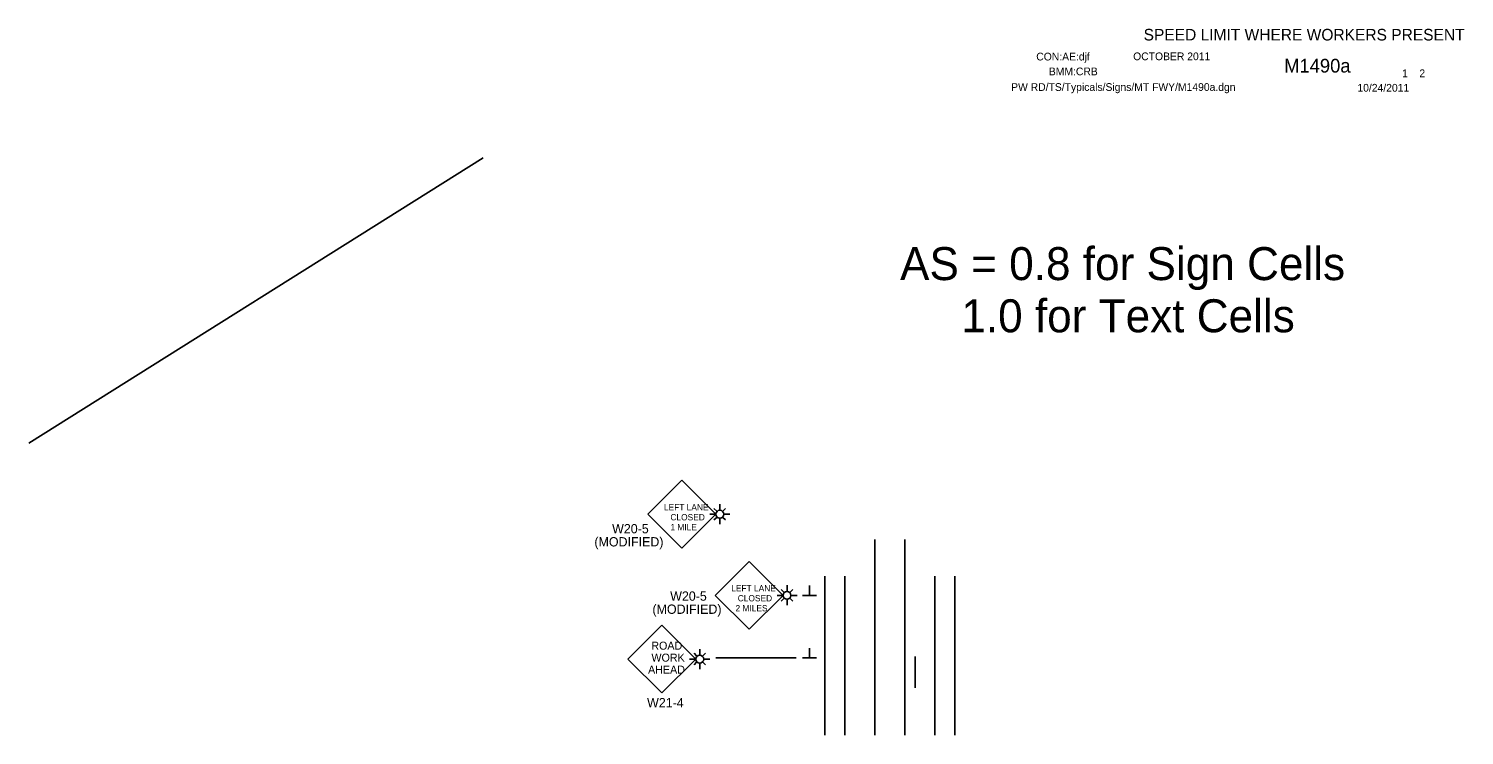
# Model space of a CAD drawing. Extents: x 16284 to 18465, y 5417 to 6974.
# Drawn here: x 16284 to 17434, y 5417 to 5984 of the extents above; entities that cross this region are included whole.
import ezdxf

# ---------------------------------------------------------------- set-up
doc = ezdxf.new("R2010")
doc.units = 0
for name, color, linetype in [('ALI_LEGAL_EX', 7, 'Continuous'), ('BORDER', 7, 'Continuous'), ('BORDER_SIGNAL_WO', 7, 'Continuous'), ('PAVT_EDGE_EX', 7, 'Continuous'), ('TRAFFIC_SIGNS_PR', 7, 'Continuous'), ('TYPICAL_TEXT_DIMEN_PR', 7, 'Continuous')]:
    doc.layers.add(name, color=color, linetype=linetype)

msp = doc.modelspace()

# ---------------------------------------------------------------- linework, layer by layer
at = {"layer": 'ALI_LEGAL_EX'}
for p, q in [((16961.5, 5574.3), (16961.5, 5417.4)), ((16985.5, 5574.3), (16985.5, 5417.4))]:
    msp.add_line(p, q, dxfattribs=at)
for points in [[(16961.5, 5544.9), (16961.5, 5519.9)], [(16985.5, 5544.9), (16985.5, 5519.9)], [(16993.6, 5480.5), (16993.6, 5455.5)], [(16961.5, 5444.9), (16961.5, 5419.9)], [(16985.5, 5444.9), (16985.5, 5419.9)]]:
    msp.add_lwpolyline(points, dxfattribs=at)
at = {"layer": 'PAVT_EDGE_EX'}
for p, q in [((16921.5, 5544.9), (16921.5, 5417.4)), ((16937.5, 5544.9), (16937.5, 5417.4)), ((17009.5, 5544.9), (17009.5, 5417.4)), ((17025.5, 5544.9), (17025.5, 5417.4))]:
    msp.add_line(p, q, dxfattribs=at)
at = {"layer": 'TRAFFIC_SIGNS_PR'}
for p, q in [((16806.9, 5621.7), (16779.7, 5594.5)), ((16834.1, 5594.5), (16806.9, 5621.7)), ((16837.3, 5598), (16837.3, 5602.5)), ((16779.7, 5594.5), (16806.9, 5567.3)), ((16806.9, 5567.3), (16834.1, 5594.5)), ((16834.1, 5594.5), (16829.2, 5594.5)), ((16834.8, 5597), (16832.6, 5599.1)), ((16834.8, 5592), (16832.6, 5589.9)), ((16837.3, 5586.5), (16837.3, 5590.9)), ((16839.8, 5597), (16841.9, 5599.1)), ((16839.8, 5592), (16841.9, 5589.9)), ((16840.4, 5594.5), (16845.3, 5594.5)), ((16860.8, 5556.7), (16833.6, 5529.5)), ((16887.9, 5529.5), (16860.8, 5556.7)), ((16888.6, 5532), (16886.5, 5534.1)), ((16891.1, 5533.1), (16891.1, 5537.6)), ((16893.6, 5532), (16895.7, 5534.1)), ((16833.6, 5529.5), (16860.8, 5502.3)), ((16860.8, 5502.3), (16887.9, 5529.5)), ((16887.9, 5529.5), (16883.1, 5529.5)), ((16888.6, 5527), (16886.5, 5524.9)), ((16891.1, 5521.6), (16891.1, 5526)), ((16893.6, 5527), (16895.7, 5524.9)), ((16894.2, 5529.5), (16899.1, 5529.5)), ((16790.8, 5505.6), (16763.7, 5478.4)), ((16818, 5478.4), (16790.8, 5505.6)), ((16821.2, 5482), (16821.2, 5486.5)), ((16763.7, 5478.4), (16790.8, 5451.3)), ((16790.8, 5451.3), (16818, 5478.4)), ((16818, 5478.4), (16813.1, 5478.4)), ((16818.7, 5481), (16816.6, 5483.1)), ((16818.7, 5475.9), (16816.6, 5473.8)), ((16821.2, 5470.5), (16821.2, 5474.9)), ((16823.7, 5481), (16825.8, 5483.1)), ((16823.7, 5475.9), (16825.8, 5473.8)), ((16824.3, 5478.4), (16829.2, 5478.4))]:
    msp.add_line(p, q, dxfattribs=at)
for centre in [(16837.3, 5594.5), (16891.1, 5529.5), (16821.2, 5478.4)]:
    msp.add_circle(centre, 3.15, dxfattribs=at)
at = {"layer": 'TYPICAL_TEXT_DIMEN_PR'}
for p, q in [((16647.8, 5880), (16283.8, 5651.4)), ((16909.1, 5529.5), (16909.1, 5537.3)), ((16903.5, 5529.5), (16914.8, 5529.5)), ((16909.1, 5479.5), (16909.1, 5487.3)), ((16834.1, 5479.5), (16898.5, 5479.5)), ((16903.5, 5479.5), (16914.8, 5479.5))]:
    msp.add_line(p, q, dxfattribs=at)

# ---------------------------------------------------------------- texts
at = {"layer": 'BORDER'}
msp.add_text('SPEED LIMIT WHERE WORKERS PRESENT', height=9.3, dxfattribs=at).set_placement((17176.7, 5974.1))
at = {"layer": 'BORDER_SIGNAL_WO'}
for s, height, p in [('CON:AE:djf  ', 6.2, (17090.7, 5958.1)), ('    OCTOBER 2011    ', 6.2, (17159.1, 5958.3)), ('    M1490a   ', 11, (17272.9, 5948.4)), ('BMM:CRB   ', 6.2, (17100.8, 5946.2)), (' 1    2 ', 6.2, (17381.4, 5944.7)), ('PW RD/TS/Typicals/Signs/MT FWY/M1490a.dgn      ', 6.2, (17070.6, 5933.7)), ('10/24/2011    ', 6.2, (17347.9, 5933.1)), ('AS = 0.8 for Sign Cells', 26.424, (16981.6, 5782.1)), ('     1.0 for Text Cells', 26.424, (16981.6, 5740.3))]:
    msp.add_text(s, height=height, dxfattribs=at).set_placement(p)
at = {"layer": 'TRAFFIC_SIGNS_PR'}
for s, height, p in [('LEFT LANE', 5.01, (16792.5, 5597.6)), ('CLOSED', 5.01, (16797.7, 5589.6)), ('(MODIFIED)', 7.45, (16736.8, 5568.7)), ('W20-5', 7.45, (16751, 5579.2)), ('1 MILE', 5.01, (16797.7, 5581.6)), ('W20-5', 7.45, (16797.5, 5525.2)), ('LEFT LANE', 5.01, (16846.4, 5532.7)), ('(MODIFIED)', 7.45, (16783.3, 5514.7)), ('2 MILES', 5.01, (16849.8, 5516.7)), ('CLOSED', 5.01, (16851.6, 5524.7)), ('ROAD', 6.41, (16782.4, 5486)), ('AHEAD', 6.41, (16779.8, 5466.8)), ('WORK', 6.41, (16782.5, 5476.4)), ('W21-4', 7.45, (16779, 5439.8))]:
    msp.add_text(s, height=height, dxfattribs=at).set_placement(p)

doc.saveas('drawing.dxf')
